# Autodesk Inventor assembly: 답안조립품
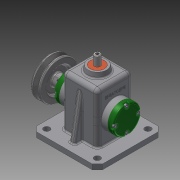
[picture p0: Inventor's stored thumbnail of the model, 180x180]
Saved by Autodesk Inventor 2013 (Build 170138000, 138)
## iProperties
Created: 2016-02
Part Number: 답안조립품
Document SubType Name: Assembly
Designer: max6
Author: max6
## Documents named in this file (16)
- C:\Documents and Settings\max6\바탕 화면\460212V1002\답안조립품.iam
- C:\Documents and Settings\max6\바탕 화면\460212V1002\1-본체.ipt
- C:\Documents and Settings\max6\바탕 화면\460212V1002\뒤커버.ipt
- C:\Documents and Settings\max6\바탕 화면\460212V1002\앞커버.ipt
- C:\Documents and Settings\max6\바탕 화면\460212V1002\베어링 12 x 32 x 10.ipt
- C:\Documents and Settings\max6\바탕 화면\460212V1002\편심축.ipt
- C:\Documents and Settings\max6\바탕 화면\460212V1002\링크.ipt
- C:\Documents and Settings\max6\바탕 화면\460212V1002\오일실 12 25 7.ipt
- C:\Documents and Settings\max6\바탕 화면\460212V1002\볼트 M4 x 12.ipt
- C:\Documents and Settings\max6\바탕 화면\460212V1002\슬라이드.ipt
- C:\Documents and Settings\max6\바탕 화면\460212V1002\핀 5 x 18.ipt
- C:\Documents and Settings\max6\바탕 화면\460212V1002\고정핀 1.2 x 10.ipt
- C:\Documents and Settings\max6\바탕 화면\460212V1002\부시.ipt
- C:\Documents and Settings\max6\바탕 화면\460212V1002\키 4 x 4 x 10.ipt
- C:\Documents and Settings\max6\바탕 화면\460212V1002\V벨트풀리.ipt
- C:\Documents and Settings\max6\바탕 화면\460212V1002\멈춤나사 M3x8.ipt
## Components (12 placed, 5 different names)
1. 1-본체:1
2. 핀 5 x 18:1
3. V벨트풀리:1 — 각도:2
4. 고정핀 1.2 x 10:1
5. ISO 4762 M4 x 12:1
6. ISO 4762 M4 x 12:3
7. ISO 4762 M4 x 12:4
8. ISO 4762 M4 x 12:5
9. ISO 4762 M4 x 12:2
10. ISO 4762 M4 x 12:6
11. ISO 4762 M4 x 12:7
12. ISO 4762 M4 x 12:8
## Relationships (1: Angle 1)
- 각도:2 [Angle]: V벨트풀리:1
